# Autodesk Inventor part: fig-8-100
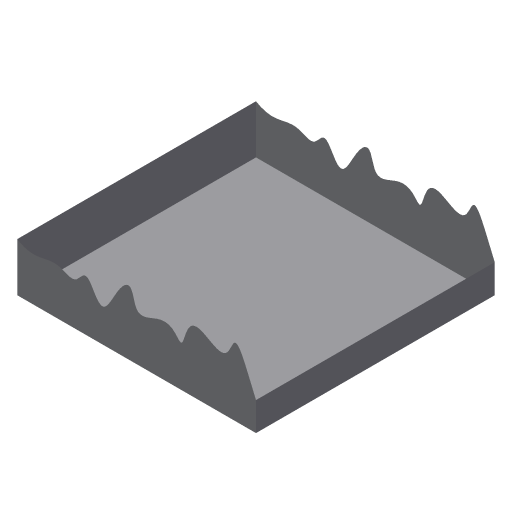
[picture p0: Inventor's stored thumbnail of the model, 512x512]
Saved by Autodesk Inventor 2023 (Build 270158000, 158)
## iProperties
Part Number: fig-8-100
Document SubType Name: Modeling
Created: 2002-12
Designer: deepak
Density: 1 g/cm^3
Material: Generic
Surface Area: 62.5725 cm^2
Appearance: Default
Control State: 0
Master: False
Checked Out: False
Shininess: 64.0
Length Units: 11269
Angle Units: 11279
Time Units: 11290
Mass Units: 11283
Length Display Precision: 3
Angle Display Precision: 2
Compacted: True
Density: 0.0
Volumn: 0.0
Area: 0.0
PropertySet Name: Model Information
Author: deepak
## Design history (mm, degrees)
sketch "Sketch1"
  geometry: L1 (-32.188, 30.089)-(27.812, 30.089); L2 (27.812, 30.089)-(27.812, -29.911); L3 (27.812, -29.911)-(-32.188, -29.911); L4 (-32.188, -29.911)-(-32.188, 30.089)
  constraints: 8 end point, 2 parallel, 1 horizontal, 1 perpendicular
  dimensions: "d0" = 60 distance of L1.start L1.end; "d1" = 60 distance of L3.end L1.start
extrude "Extrusion1" new body sketch "Sketch1" stored distance "d2" = 20; taper "d3" = 0 deg
sketch "Sketch2"
  geometry: 17 further points
  constraints: 17 other
extrude_surface "ExtrusionSrf1" sketch "Sketch2" dims "d4" = 70, "d5" = 0
split "Split1"
delete_face "Delete Face2"
body "Solid1"
body "Srf1"
